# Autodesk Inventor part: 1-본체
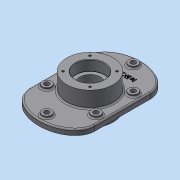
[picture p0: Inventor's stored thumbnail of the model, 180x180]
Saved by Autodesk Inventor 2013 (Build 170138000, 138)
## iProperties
Created: 2015-02
Part Number: 1-본체
Material: 일반
Document SubType Name: Modeling
Designer: dgall
Density: 1 g/cm^3
Author: dgall
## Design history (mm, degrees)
sketch "스케치1" dims "d84" = 50, "d85" = 50
  geometry: L1 (-70, 60)-(70, 60); L2 (70, 60)-(70, -60); L3 (70, -60)-(-70, -60); L4 (-70, -60)-(-70, 60); 5 further points; 2 other entities
  constraints: 8 end point, 3 horizontal, 3 midpoint, 2 parallel, 1 coincident, 1 horizontal alignment, 1 perpendicular, 1 vertical alignment, 8 other
  dimensions: "d0" = 120 distance of L3.end L1.start; "d3" = 140 distance between parallel lines of L2 L4
extrude "돌출1" new body sketch "스케치1" distance "d6" = 12; taper "d7" = 0 deg
sketch "스케치2"
  geometry: C1 r 50 at (0, 0); 1 further point
  constraints: 1 centre point, 1 coincident
  dimensions: "d8" = 100 diameter of C1
extrude "돌출2" join sketch "스케치2" distance "d10" = 23; taper "d11" = 0 deg
sketch "스케치3"
  geometry: C1 r 50 at (0, 0) reference; C2 r 31 at (0, 0)
  constraints: 1 centre point, 1 coincident
  dimensions: "d12" = 62 diameter of C2
extrude "돌출3" cut sketch "스케치3" distance "d14" = 22; taper "d15" = 0 deg
sketch "스케치4"
  geometry: C1 r 50 at (0, 0); 1 further point
  constraints: 1 centre point, 1 coincident
  dimensions: "d16" = 100 diameter of C1
extrude "돌출4" join sketch "스케치4" distance "d18" = 35; taper "d19" = 0 deg
sketch "스케치5"
  geometry: C1 r 50 at (0, 0) reference; C2 r 31 at (0, 0)
  constraints: 1 centre point, 1 coincident
  dimensions: "d20" = 62 diameter of C2
extrude "돌출5" cut sketch "스케치5" distance "d22" = 22; taper "d23" = 0 deg
sketch "스케치6"
  geometry: C1 r 50 at (0, 0) reference; C2 r 22.5 at (0, 0)
  constraints: 1 centre point, 1 coincident
  dimensions: "d24" = 45 diameter of C2
extrude "돌출6" cut sketch "스케치6" stored distance "d26" = 22; taper "d27" = 0 deg
chamfer "모따기1" distance "d28" = 1; stored, may be unused: second distance "d29" = 2, angle "d30" = 45 deg
fillet "모깎기1" dims "d31" = 0.3
sketch "스케치7"
  geometry: L1 (0, 0)-(-41, 0); L2 (0, 0)-(-53.009, 53.009); C1 r 32 at (0, 0) reference; C2 r 3 at (-28.991, 28.991); A1 r 41 centre (0, 0) between (-41, 0) and (-28.991, 28.991)
  constraints: 4 end point, 2 centre point, 2 point on circle, 1 coincident, 1 horizontal, 1 point on line
  dimensions: "d33" = 82 diameter of A1; "d36" = 45 deg angle of L2 L1; "d38" = 6 diameter of C2
hole "구멍1" sketch "스케치7" at (-28.991, 28.991) diameter "d39" = 4.917; stored, may be unused: countersink angle "d43" = 90 deg, drill point angle "d45" = 118 deg; dims "d40" = 10, "d41" = 4, "d42" = 2, "d44" = 13
fillet "모깎기3" dims "d49" = 3
node "작업 평면2"
sketch "스케치8"
  geometry: L1 (-70, 60)-(-70, -60) reference; L2 (70, -60)-(70, 60) reference; L3 (-53, -56.976)-(-53, 56.976); L4 (53, 56.976)-(53, -56.976); C1 r 10 at (0, -93); C2 r 10 at (0, 93); C3 r 10 at (53, -39.976); C4 r 10 at (53, 39.976); C5 r 10 at (-53, 39.976); C6 r 10 at (-53, -39.976); A1 r 74 centre (0, -36) between (-70, -60) and (70, -60) reference; A2 r 74 centre (0, 36) between (70, 60) and (-70, 60) reference; A3 r 57 centre (0, 36) between (53, 56.976) and (-53, 56.976); A4 r 57 centre (0, -36) between (-53, -56.976) and (53, -56.976)
  constraints: 8 centre point, 6 point on circle, 4 end point, 4 point on line, 3 equal radius, 1 vertical alignment, 3 other
  dimensions: "d50" = 17 distance between parallel lines of L1 L3; "d51" = 20 diameter of C1; "d52" = 20 diameter of C2; "d54" = 20 diameter of C3; "d55" = 17 distance of L4.end C3.centre; "d56" = 17 distance of L4.start C4.centre; "d57" = 17 distance of L3.end C5.centre; "d58" = 17 distance of L3.start C6.centre
extrude "돌출7" join sketch "스케치8" distance "d59" = 5; taper "d60" = 0 deg
fillet "모깎기4" dims "d61" = 3
fillet "모깎기5" dims "d62" = 3
sketch "스케치9"
  geometry: C1 r 10 at (0, 0) reference; C2 r 5.5 at (0, 0); 1 further point
  constraints: 1 centre point, 1 coincident
  dimensions: "d63" = 11 diameter of C2
extrude "돌출8" cut sketch "스케치9" stored distance "d65" = 5; taper "d66" = 0 deg
sketch "스케치10"
  geometry: C1 r 10 at (0, 0) reference; C2 r 5.5 at (0, 0); 1 further point
  constraints: 1 centre point, 1 coincident
  dimensions: "d67" = 11 diameter of C2
extrude "돌출9" cut sketch "스케치10" stored distance "d69" = 5; taper "d70" = 0 deg
sketch "스케치11"
  geometry: C1 r 10 at (0, 0) reference; C2 r 5.5 at (0, 0); C3 r 10 at (106, 0) reference; C4 r 5.5 at (106, 0); 1 further point
  constraints: 2 centre point, 2 coincident, 1 equal radius
  dimensions: "d77" = 11 diameter of C2
extrude "돌출10" cut sketch "스케치11" stored distance "d79" = 5; taper "d80" = 0 deg
sketch "스케치12"
  geometry: C1 r 53 at (0, 0) reference; A1 r 71 centre (0, 36) between (67, 59.495) and (-67, 59.495) reference; 1 further point
  constraints: 1 vertical alignment, 1 other
  dimensions: "d81" = 65 distance of C1.centre point (0, 65)
feature "엠보싱1" sketch "스케치12" dims "d0" = 120, "d3" = 140, "d18" = 35, "d82" = 1, "d83" = 0, "d84" = 50, "d85" = 50
node "솔리드1"
pattern_circular "원형 패턴1" dims angle "d47" = 360 deg
mirror "대칭1"
pattern_circular "원형 패턴2" dims angle "d72" = 360 deg
pattern_linear "직사각형 패턴1" dims "d76" = 106
